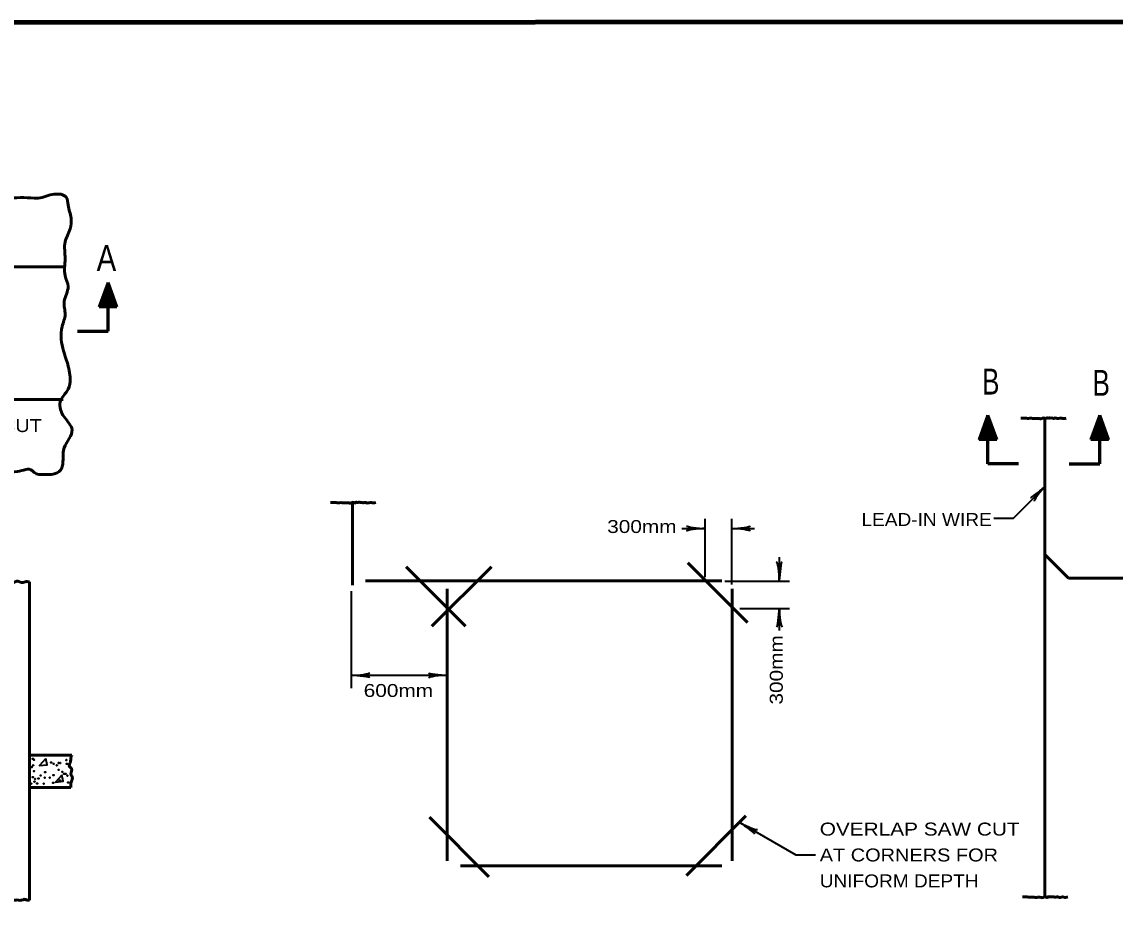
# Model space of a CAD drawing. Extents: x -90 to 623, y -379 to 75.
# Drawn here: x 208.1 to 376.8, y -69 to 69.4 of the extents above; entities that cross this region are included whole.
import ezdxf

# ---------------------------------------------------------------- set-up
doc = ezdxf.new("R2010")
doc.units = 0
doc.header["$LTSCALE"] = 0.8
doc.layers.add('1', color=7, linetype='Continuous', lineweight=35)

msp = doc.modelspace()

# ---------------------------------------------------------------- linework, layer by layer
at = {"layer": '1', "lineweight": 53}
for p, q in [((214.4592, 31.5949), (193.9592, 31.5949)), ((221.3807, 29.1601), (220.0126, 25.4013)), ((221.3807, 29.1601), (222.7488, 25.4013)), ((220.1598, 25.5852), (220.9852, 27.4662)), ((220.0126, 25.4013), (222.7488, 25.4013)), ((220.5821, 26.2378), (222.5974, 25.5661)), ((222.156, 26.1611), (220.8508, 26.1994)), ((357.1889, 8.6589), (355.8208, 4.9002)), ((357.1889, 8.6589), (358.557, 4.9002)), ((374.4443, 8.6589), (373.0762, 4.9002)), ((374.4443, 8.6589), (375.8123, 4.9002)), ((358.4097, 5.0841), (357.5844, 6.9651)), ((365.9924, 8.0001), (365.9924, -65.7447)), ((373.2234, 5.0841), (374.0487, 6.9651)), ((357.9875, 5.7367), (355.9722, 5.0649)), ((356.4136, 5.6599), (357.7188, 5.6982)), ((373.6457, 5.7367), (375.661, 5.0649)), ((375.2196, 5.6599), (373.9144, 5.6982)), ((358.557, 4.9002), (355.8208, 4.9002)), ((373.0762, 4.9002), (375.8123, 4.9002)), ((259.1281, -4.8118), (259.1281, -17.5567)), ((369.6012, -16.4908), (366.0657, -12.9553)), ((276.5712, -23.9092), (267.3787, -14.7167)), ((271.3582, -23.9091), (280.5507, -14.7167)), ((320.0787, -23.3077), (310.8862, -14.1152)), ((369.6012, -16.4908), (422.1311, -16.4908)), ((209.2523, -66.201), (209.2523, -17.0762)), ((261.133, -16.8918), (316.133, -16.8918)), ((273.7271, -60.1245), (273.7271, -18.1245)), ((317.7271, -60.1245), (317.7271, -18.1245)), ((215.8137, -43.8166), (209.1953, -43.8166)), ((215.6602, -48.8166), (209.2523, -48.8166)), ((280.1801, -62.6047), (270.9877, -53.4123)), ((310.6553, -62.4042), (319.8477, -53.2118)), ((275.7692, -60.8918), (316.133, -60.8918))]:
    msp.add_line(p, q, dxfattribs=at)
at = {"layer": '1', "lineweight": 60}
for p, q in [((221.3807, 21.6601), (221.3807, 29.1601)), ((216.6665, 21.6601), (221.3807, 21.6601)), ((357.1889, 1.1589), (357.1889, 8.6589)), ((374.4443, 1.1589), (374.4443, 8.6589)), ((361.9031, 1.1589), (357.1889, 1.1589)), ((369.7301, 1.1589), (374.4443, 1.1589))]:
    msp.add_line(p, q, dxfattribs=at)
at = {"layer": '1'}
for p, q in [((313.5626, -16.3403), (313.5626, -7.3403)), ((317.6728, -17.4431), (317.6728, -7.3403)), ((309.9537, -8.8217), (313.5626, -8.8217)), ((317.6728, -8.8217), (321.1814, -8.8217)), ((324.9908, -13.2327), (324.9908, -16.8416)), ((258.9276, -18.4958), (258.9276, -33.4958)), ((316.57, -16.9418), (326.57, -16.9418)), ((318.8757, -21.1522), (326.57, -21.1522)), ((324.9908, -21.1522), (324.9908, -24.5607)), ((258.9276, -31.4898), (273.7271, -31.4898))]:
    msp.add_line(p, q, dxfattribs=at)
at = {"layer": '1', "lineweight": 158}
msp.add_lwpolyline([(617.1938, 69.4188), (-42.5562, 69.3355), (-42.4728, -368.9978)], dxfattribs=at)
at = {"layer": '1', "lineweight": 53}
for points in [[(221.1579, 28.3299), (221.5226, 28.5027), (221.1962, 28.4835), (221.465, 28.5795), (221.3114, 28.6371), (221.4458, 28.7138), (221.2922, 28.829), (220.1214, 25.5085), (221.3498, 28.7714), (220.179, 25.5468), (221.369, 28.6371), (220.3326, 25.6044), (221.1003, 27.9077), (220.1983, 25.6044), (221.4458, 28.8097), (222.6358, 25.4701), (221.4458, 28.6178), (222.5207, 25.662), (221.5417, 28.1188), (222.3287, 25.9307), (221.4266, 28.234), (222.1752, 26.1035), (221.8105, 26.0459), (222.2903, 25.854), (220.3902, 25.7964)], [(220.1022, 25.4701), (222.5974, 25.4701), (222.5782, 25.5661), (220.1598, 25.5468), (222.5014, 25.6237), (220.1598, 25.6428), (222.4631, 25.7004), (220.2366, 25.758), (222.4247, 25.8156), (220.3326, 25.7196), (222.5207, 25.7196), (222.3862, 25.9307), (220.275, 25.8732), (222.3671, 26.0075), (220.3709, 26.0075), (222.2519, 26.1418), (220.4093, 26.1227), (222.3287, 26.2187), (220.4861, 26.257), (222.2711, 26.3338), (220.4861, 26.3722), (222.2519, 26.4106), (220.5053, 26.4682), (222.1752, 26.5066), (220.5053, 26.5449), (222.156, 26.5642), (220.6397, 26.6025), (222.1368, 26.6601), (220.5821, 26.6601), (222.06, 26.7752), (220.6012, 26.7369), (222.0408, 26.852), (220.6012, 26.8137), (222.06, 26.9288), (220.6397, 26.9096), (222.06, 27.0247), (220.6781, 27.0056), (222.0024, 27.1016), (220.7164, 27.1207), (222.0024, 27.1783)], [(222.0024, 27.1783), (220.8124, 27.2359), (221.9257, 27.2935), (220.8124, 27.3511), (221.8488, 27.3702), (220.87, 27.4278), (221.8105, 27.447), (220.966, 27.5238), (221.8105, 27.5622), (220.8892, 27.6197), (221.7529, 27.6773), (220.9852, 27.7157), (221.7721, 27.7349), (220.966, 27.8309), (221.6569, 27.8309), (221.0427, 27.9269), (221.6953, 27.9269), (221.1003, 28.0037), (221.5993, 28.0804), (221.1195, 28.0804), (221.5802, 28.1572), (221.1962, 28.234), (221.5802, 28.2916), (221.1195, 28.1572)], [(220.4093, 25.9116), (220.7164, 25.9307), (220.8508, 26.1994)], [(193.9592, 18.0949), (193.9592, 11.0949), (214.4592, 11.0949)], [(357.4117, 7.8287), (357.047, 8.0015), (357.3733, 7.9823), (357.1046, 8.0783), (357.2582, 8.1359), (357.1237, 8.2127), (357.2773, 8.3278), (358.4482, 5.0073), (357.2197, 8.2702), (358.3906, 5.0457), (357.2006, 8.1359), (358.237, 5.1033), (357.4692, 7.4065), (358.3713, 5.1033), (357.1237, 8.3086), (355.9337, 4.9689), (357.1237, 8.1167), (356.0489, 5.1608), (357.0278, 7.6177), (356.2409, 5.4296), (357.143, 7.7328), (356.3944, 5.6023), (356.7591, 5.5447), (356.2792, 5.3528), (358.1794, 5.2953)], [(356.5672, 6.6772), (357.7572, 6.7348), (356.6439, 6.7923), (357.7572, 6.8499), (356.7208, 6.8691), (357.6996, 6.9267), (356.7591, 6.9458), (357.6036, 7.0227), (356.7591, 7.061), (357.6804, 7.1186), (356.8167, 7.1762), (357.5844, 7.2146), (356.7975, 7.2337), (357.6036, 7.3297), (356.9127, 7.3297), (357.5268, 7.4257), (356.8742, 7.4257), (357.4692, 7.5025), (356.9702, 7.5793), (357.4501, 7.5793), (356.9894, 7.656), (357.3733, 7.7328), (356.9894, 7.7904), (357.4501, 7.656)], [(374.2215, 7.8287), (374.5862, 8.0015), (374.2598, 7.9823), (374.5286, 8.0783), (374.375, 8.1359), (374.5094, 8.2127), (374.3558, 8.3278), (373.185, 5.0073), (374.4134, 8.2702), (373.2426, 5.0457), (374.4326, 8.1359), (373.3962, 5.1033), (374.1639, 7.4065), (373.2618, 5.1033), (374.5094, 8.3086), (375.6994, 4.9689), (374.5094, 8.1167), (375.5842, 5.1608), (374.6053, 7.6177), (375.3922, 5.4296), (374.4902, 7.7328), (375.2387, 5.6023), (374.8741, 5.5447), (375.3539, 5.3528), (373.4538, 5.2953)], [(375.066, 6.6772), (373.876, 6.7348), (374.9892, 6.7923), (373.876, 6.8499), (374.9124, 6.8691), (373.9336, 6.9267), (374.8741, 6.9458), (374.0296, 7.0227), (374.8741, 7.061), (373.9527, 7.1186), (374.8165, 7.1762), (374.0487, 7.2146), (374.8357, 7.2337), (374.0296, 7.3297), (374.7205, 7.3297), (374.1063, 7.4257), (374.7589, 7.4257), (374.1639, 7.5025), (374.6629, 7.5793), (374.1831, 7.5793), (374.6438, 7.656), (374.2598, 7.7328), (374.6438, 7.7904), (374.1831, 7.656)], [(358.4673, 4.9689), (355.9722, 4.9689), (355.9913, 5.0649), (358.4097, 5.0457), (356.0682, 5.1225), (358.4097, 5.1417), (356.1065, 5.1993), (358.333, 5.2568), (356.1449, 5.3144), (358.237, 5.2184), (356.0489, 5.2184), (356.1833, 5.4296), (358.2946, 5.372), (356.2025, 5.5063), (358.1987, 5.5063), (356.3177, 5.6407), (358.1602, 5.6215), (356.2409, 5.7175), (358.0835, 5.7558), (356.2985, 5.8327), (358.0835, 5.871), (356.3177, 5.9094), (358.0643, 5.967), (356.3944, 6.0054), (358.0643, 6.0438), (356.4136, 6.063), (357.9299, 6.1013), (356.4328, 6.1589), (357.9875, 6.1589), (356.5096, 6.2741), (357.9683, 6.2357), (356.5288, 6.3508), (357.9683, 6.3125), (356.5096, 6.4277), (357.9299, 6.4084), (356.5096, 6.5236), (357.8915, 6.5044), (356.5672, 6.6004), (357.8532, 6.6196), (356.5672, 6.6772)], [(358.1602, 5.4104), (357.8532, 5.4296), (357.7188, 5.6982)], [(373.1658, 4.9689), (375.661, 4.9689), (375.6418, 5.0649), (373.2234, 5.0457), (375.565, 5.1225), (373.2234, 5.1417), (375.5267, 5.1993), (373.3002, 5.2568), (375.4882, 5.3144), (373.3962, 5.2184), (375.5842, 5.2184), (375.4498, 5.4296), (373.3386, 5.372), (375.4307, 5.5063), (373.4345, 5.5063), (375.3155, 5.6407), (373.4729, 5.6215), (375.3922, 5.7175), (373.5497, 5.7558), (375.3347, 5.8327), (373.5497, 5.871), (375.3155, 5.9094), (373.5689, 5.967), (375.2387, 6.0054), (373.5689, 6.0438), (375.2196, 6.063), (373.7032, 6.1013), (375.2003, 6.1589), (373.6457, 6.1589), (375.1236, 6.2741), (373.6648, 6.2357), (375.1044, 6.3508), (373.6648, 6.3125), (375.1236, 6.4277), (373.7032, 6.4084), (375.1236, 6.5236), (373.7417, 6.5044), (375.066, 6.6004), (373.78, 6.6196), (375.066, 6.6772)], [(373.4729, 5.4104), (373.78, 5.4296), (373.9144, 5.6982)]]:
    msp.add_lwpolyline(points, dxfattribs=at)
at = {"layer": '1'}
for points in [[(358.1262, -7.2317), (361.1262, -7.2317), (366.0759, -2.2819)], [(211.7451, -44.4027), (210.8237, -45.4392), (212.0137, -45.324), (211.7834, -44.3259)], [(214.2019, -46.9363), (213.2806, -47.9728), (214.4706, -47.8577), (214.2403, -46.8596)], [(318.901, -54.2206), (327.5612, -59.2206), (330.5612, -59.2206)]]:
    msp.add_lwpolyline(points, dxfattribs=at)
for centre in [(209.7682, -44.3832), (209.8449, -45.3813), (209.9601, -44.5367), (212.6089, -44.9589), (212.9928, -45.1509), (213.4918, -45.3813), (213.7605, -45.0358), (213.9908, -45.0358), (214.9506, -44.5751), (215.0273, -45.1509), (209.2308, -45.9954), (209.5762, -45.6883), (209.7682, -47.2238), (209.9601, -46.3025), (210.9966, -46.9552), (211.6108, -47.3006), (211.6876, -46.4561), (212.3786, -47.3006), (212.9544, -46.9168), (213.7605, -46.0722), (214.3363, -46.3793), (214.6051, -46.6864), (214.8354, -46.6864), (215.1041, -46.9935), (209.5378, -48.2219), (210.0369, -47.9148), (210.1137, -47.4926), (210.4592, -48.1836), (210.6511, -47.4157), (211.4572, -48.2219), (212.916, -48.1067), (213.9525, -47.7229), (215.2192, -48.03)]:
    msp.add_circle(centre, 0.0607, dxfattribs=at)
at = {"layer": '1', "lineweight": 40}
for centre, major_axis, ratio, start_param, end_param in [((365.134, -2.9246), (-1.3662, -1.1178), 0.07063, 6.28230741, 8.55970261), ((365.4997, -3.2489), (1.1523, 1.3731), 0.122415, 0.89635335, 3.14159265), ((312.4421, -8.6101), (1.7565, -0.1757), 0.07063, 3.14071475, 5.41810995), ((318.7639, -8.5455), (-1.7857, -0.1562), 0.122415, 0.89635335, 3.14159265), ((312.4714, -9.098), (1.7857, 0.1562), 0.122415, 0.89635335, 3.14159265), ((318.7933, -9.0334), (1.7565, -0.1757), 0.07063, 6.28230741, 8.55970261), ((324.7145, -15.7504), (0.1562, -1.7857), 0.122415, 0.89635335, 3.14159265), ((325.2024, -15.7211), (0.1757, 1.7565), 0.07063, 6.28230741, 8.55970261), ((324.7792, -22.2728), (-0.1757, -1.7565), 0.07063, 6.28230741, 8.55970261), ((325.2671, -22.2434), (-0.1562, 1.7857), 0.122415, 0.89635335, 3.14159265), ((260.0481, -31.7014), (1.7565, -0.1757), 0.07063, 6.28230741, 8.55970261), ((260.0188, -31.2135), (-1.7857, -0.1562), 0.122415, 0.89635335, 3.14159265), ((272.6359, -31.7661), (1.7857, 0.1562), 0.122415, 0.89635335, 3.14159265), ((272.6066, -31.2782), (1.7565, -0.1757), 0.07063, 3.14071475, 5.41810995), ((319.7656, -54.9641), (1.4333, -1.0303), 0.07063, 6.28230741, 8.55970261), ((319.9842, -54.5269), (-1.6245, 0.7576), 0.122415, 0.89635335, 3.14159265)]:
    msp.add_ellipse(centre, major_axis=major_axis, ratio=ratio, start_param=start_param, end_param=end_param, dxfattribs=at)
at = {"layer": '1', "lineweight": 53}
for points in [[(214.1523, 42.8104), (214.92, 42.3498), (215.2272, 41.1214), (215.6877, 39.1253), (215.5342, 37.4363), (214.7665, 35.4401), (214.7665, 32.8298), (214.7665, 30.2195), (215.2272, 28.5304), (214.6129, 26.2272), (214.7665, 24.2311), (214.3058, 22.3885), (214.1523, 20.3924), (215.0736, 16.8608), (215.5342, 14.2505), (215.2272, 12.715), (213.9988, 10.7189), (214.6129, 8.4157), (215.8413, 6.4196), (214.6129, 3.6557), (214.3058, 0.7382), (213.9988, 0.1241), (211.542, -0.4901), (210.0065, -0.183), (209.6994, 0.1241), (207.3962, -0.0295), (206.1678, 0.2777), (206.0143, 0.5847), (204.0182, 0.7382), (203.4039, 0.8918), (202.4827, 1.3525), (200.7936, 0.5847), (198.7975, -0.3366), (195.8801, 0.1241), (194.4982, 0.1241), (190.813, 0.4312), (189.4311, 0.4312), (188.3562, 0.8918), (187.8956, 1.6596), (185.4388, 0.7382), (184.9782, 0.4312), (184.0569, -0.0295), (181.9073, -0.0295), (181.4466, 0.5847), (180.3717, 0.5847), (178.5292, -0.0295), (177.3007, 0.4312), (175.4582, 0.4312), (172.8479, 0.2777), (171.1588, 0.2777), (168.0879, 0.2777), (166.0917, 0.2777), (164.5563, 0.2777), (162.7138, 0.4312), (160.1034, 0.4312), (157.3396, 0.2777), (154.5757, -0.0295), (153.9615, 0.2777), (151.5048, -0.0295), (150.5834, -0.0295), (149.5086, -0.3366), (148.2802, -0.3366), (147.5125, 1.0453), (145.2092, -0.3366), (143.5203, -0.183), (142.1383, -0.3366), (140.6028, -0.3366), (138.4532, -0.0295), (136.9177, -0.183), (135.5358, -0.183), (134.1538, 0.4312), (132.3113, -0.3366), (131.5435, 0.1241), (129.0867, -0.0295), (126.3228, -0.183), (125.0945, 0.8918), (123.559, -0.183), (120.6416, 0.1241), (120.6416, 0.2777), (120.9487, 2.4273), (120.488, 5.3447), (120.7952, 6.8802), (120.6416, 9.3369), (118.9526, 10.4117), (119.5667, 14.8647), (119.7203, 16.7072), (119.4132, 19.164), (119.8738, 21.6208), (119.7203, 23.3098), (119.7203, 26.995), (120.488, 29.4518), (119.4132, 31.1408), (119.7203, 33.2904), (119.4132, 34.9795), (120.1809, 36.9756), (119.5667, 39.1253), (120.2778, 42.0949)], [(120.2778, 42.0949), (122.6377, 41.8891), (125.8622, 42.1962), (126.6299, 42.0427), (132.0042, 42.1962), (137.6854, 42.3498), (139.0673, 42.0427), (142.1383, 42.1962), (143.9808, 42.3498), (146.8982, 42.5033), (148.8944, 42.1962), (151.8118, 42.5033), (154.5757, 42.6568), (155.8041, 42.0427), (157.9537, 41.8891), (159.9498, 42.6568), (161.7924, 43.2711), (164.0957, 42.3498), (167.3202, 42.0427), (169.6234, 42.3498), (170.2376, 42.5033), (171.1588, 42.6568), (172.8479, 42.5033), (174.5369, 42.6568), (176.0724, 42.5033), (178.5292, 42.3498), (179.604, 41.8891), (179.9111, 41.1214), (181.9073, 41.582), (182.0607, 41.582), (183.1356, 40.5072), (187.2814, 42.5033), (189.2775, 42.5033), (191.2737, 42.0427), (192.502, 42.0427), (196.0337, 42.0427), (196.1872, 42.1962), (197.4156, 43.2711), (198.3368, 43.5782), (200.1794, 42.8104), (202.7897, 42.0427), (204.3252, 41.7356), (205.7072, 42.0427), (210.0065, 42.1962), (210.6207, 42.1962), (213.0774, 42.8104), (214.1523, 42.8104)], [(362.2842, 8.2205), (362.8356, 8.2332), (363.1614, 8.2082), (363.4371, 8.1832), (363.9133, 8.2082), (364.214, 8.1581), (364.4646, 8.1581), (364.7653, 8.1832), (365.1663, 8.1581), (365.3417, 8.1079), (365.4169, 8.133), (365.4922, 8.1581), (365.7929, 8.2583), (365.9182, 8.1832), (366.0937, 8.1581), (366.244, 8.2583), (366.3693, 8.2583), (366.4696, 8.2082), (366.6199, 8.2583), (366.8706, 8.2332), (367.1713, 8.2332), (367.2465, 8.1832), (367.4971, 8.2082), (367.7727, 8.2332), (367.848, 8.1832), (368.0986, 8.1581), (368.4494, 8.2332), (368.5497, 8.2332), (368.675, 8.1832), (368.9006, 8.1581), (369.2842, 8.2205)], [(255.7197, -4.8118), (256.2711, -4.7991), (256.5969, -4.8242), (256.8726, -4.8492), (257.3487, -4.8242), (257.6495, -4.8742), (257.9001, -4.8742), (258.2008, -4.8492), (258.6018, -4.8742), (258.7772, -4.9244), (258.8524, -4.8993), (258.9277, -4.8742), (259.2284, -4.774), (259.3537, -4.8492), (259.5292, -4.8742), (259.6795, -4.774), (259.8048, -4.774), (259.9051, -4.8242), (260.0554, -4.774), (260.3061, -4.7991), (260.6068, -4.7991), (260.682, -4.8492), (260.9326, -4.8242), (261.2082, -4.7991), (261.2835, -4.8492), (261.5341, -4.8742), (261.8849, -4.7991), (261.9852, -4.7991), (262.1105, -4.8492), (262.3361, -4.8742), (262.7197, -4.8118)], [(201.2523, -17.0762), (202.0042, -17.1688), (202.3784, -17.079), (203.1119, -17.1089), (203.576, -17.1089), (203.7856, -16.9742), (204.3844, -17.064), (204.9982, -17.1389), (205.2378, -17.0341), (205.8515, -17.0491), (206.2856, -17.0341), (206.5401, -17.1538), (207.0342, -17.064), (207.1389, -17.0042), (207.4982, -16.9742), (207.6778, -17.0191), (208.0222, -17.1389), (208.5761, -17.079), (208.7558, -17.0191), (209.0551, -17.0341), (209.2523, -17.0762)], [(215.8137, -43.8166), (215.6602, -44.192), (215.5835, -44.8829), (215.43, -45.5739), (215.7371, -45.881), (215.6602, -46.7256), (215.8906, -47.3397), (215.6602, -48.1075), (215.6602, -48.6449), (215.6602, -48.822)], [(362.5348, -65.7129), (363.0863, -65.7002), (363.4121, -65.7253), (363.6877, -65.7502), (364.1639, -65.7253), (364.4647, -65.7753), (364.7152, -65.7753), (365.016, -65.7502), (365.417, -65.7753), (365.5924, -65.8255), (365.6676, -65.8004), (365.7428, -65.7753), (366.0436, -65.6751), (366.1688, -65.7502), (366.3443, -65.7753), (366.4947, -65.6751), (366.62, -65.6751), (366.7202, -65.7253), (366.8706, -65.6751), (367.1212, -65.7002), (367.422, -65.7002), (367.4972, -65.7502), (367.7477, -65.7253), (368.0234, -65.7002), (368.0987, -65.7502), (368.3492, -65.7753), (368.7001, -65.7002), (368.8003, -65.7002), (368.9257, -65.7502), (369.1513, -65.7753), (369.5348, -65.7129)], [(201.2523, -66.201), (201.8918, -66.0967), (202.3409, -66.0517), (203.2841, -66.2164), (203.4638, -66.0218), (203.9427, -66.1566), (204.332, -66.2015), (204.6912, -66.2015), (205.0356, -66.2015), (205.1553, -66.1267), (205.7392, -66.0517), (205.859, -66.2464), (206.1583, -66.2913), (206.6075, -66.2763), (206.8919, -66.2164), (207.0267, -66.2164), (207.371, -66.1715), (207.7602, -66.2464), (208.1045, -66.1865), (208.2692, -66.1566), (208.5087, -66.0817), (208.7632, -66.1416), (209.0177, -66.2314), (209.2523, -66.201)]]:
    msp.add_spline(points, degree=3, dxfattribs=at)

# ---------------------------------------------------------------- texts
at = {"layer": '1'}
for s, height, width, p in [('A', 4, 0.85, (219.6241, 30.935)), ('B', 4, 0.75, (356.2929, 11.8712)), ('B', 4, 0.75, (373.3352, 11.6707)), ('SAW CUT', 2, 1.15, (196.9911, 6.0724)), ('LEAD-IN WIRE', 2, 1.1, (337.6757, -8.4322)), ('300mm', 2, 1.2, (298.4273, -9.5128)), ('600mm', 2, 1.2, (260.8459, -34.8318)), ('OVERLAP SAW CUT', 2, 1.2, (331.2315, -56.233)), ('AT CORNERS FOR', 2, 1.15, (331.2315, -60.233)), ('UNIFORM DEPTH', 2, 1.1, (331.2315, -64.233))]:
    msp.add_text(s, height=height, dxfattribs=dict(at, width=width)).set_placement(p)
at = {"layer": '1', "width": 1.2}
msp.add_text('300mm', height=2, rotation=90, dxfattribs=at).set_placement((325.5246, -36.0024))

doc.saveas('drawing.dxf')
